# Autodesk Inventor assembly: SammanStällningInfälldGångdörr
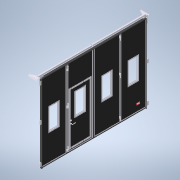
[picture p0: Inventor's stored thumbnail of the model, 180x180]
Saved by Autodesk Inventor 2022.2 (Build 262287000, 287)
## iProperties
Created: 2022-02
Part Number: SammanStällningInfälldGångdörr
Document SubType Name: Assembly
Designer: cl
Author: cl
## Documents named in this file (20)
- G:\AutoCad\Carl Lund\3D-modeller systemlösningar\3D-modell-systemlösning-2022\SammanStällningInfälldGångdörr.iam
- G:\AutoCad\Carl Lund\3D-modeller systemlösningar\3D-modell-systemlösning-2022\Parts\BladKomplett2022.iam
- G:\AutoCad\Carl Lund\3D-modeller systemlösningar\3D-modell-systemlösning-2022\Parts\MellanGångjärnH.ipt
- G:\AutoCad\Carl Lund\3D-modeller systemlösningar\3D-modell-systemlösning-2022\Parts\MellanGångjärnV.ipt
- G:\AutoCad\Carl Lund\3D-modeller systemlösningar\3D-modell-systemlösning-2022\Parts\Karmstyrning.ipt
- G:\AutoCad\Carl Lund\3D-modeller systemlösningar\3D-modell-systemlösning-2022\Parts\KarmgångjärnH.ipt
- G:\AutoCad\Carl Lund\3D-modeller systemlösningar\3D-modell-systemlösning-2022\Parts\KarmgångjärnV.ipt
- G:\AutoCad\Carl Lund\3D-modeller systemlösningar\3D-modell-systemlösning-2022\Parts\SidotätningUppe.ipt
- G:\AutoCad\Carl Lund\3D-modeller systemlösningar\3D-modell-systemlösning-2022\Parts\SidoTätning.ipt
- G:\AutoCad\Carl Lund\3D-modeller systemlösningar\3D-modell-systemlösning-2022\Parts\SläpList.ipt
- G:\AutoCad\Carl Lund\3D-modeller systemlösningar\3D-modell-systemlösning-2022\Parts\GummilistMellan.ipt
- G:\AutoCad\Carl Lund\3D-modeller systemlösningar\3D-modell-systemlösning-2022\Styrande.iam
- G:\AutoCad\Carl Lund\3D-modeller systemlösningar\3D-modell-systemlösning-2022\Parts\GarageregelHöger.ipt
- G:\AutoCad\Carl Lund\3D-modeller systemlösningar\3D-modell-systemlösning-2022\Parts\GarageregelVänster.ipt
- G:\AutoCad\Carl Lund\3D-modeller systemlösningar\3D-modell-systemlösning-2022\Parts\UppställningsbeslagHöger.ipt
- G:\AutoCad\Carl Lund\3D-modeller systemlösningar\3D-modell-systemlösning-2022\Parts\UppställningsbeslagVänster.ipt
- G:\AutoCad\Carl Lund\3D-modeller systemlösningar\3D-modell-systemlösning-2022\Parts\styrrulle.ipt
- G:\AutoCad\Carl Lund\3D-modeller systemlösningar\3D-modell-systemlösning-2022\Parts\Styrskena.ipt
- G:\AutoCad\Carl Lund\3D-modeller systemlösningar\3D-modell-systemlösning-2022\Parts\BladKomplettInfälld2022.iam
- G:\AutoCad\Carl Lund\3D-modeller systemlösningar\3D-modell-systemlösning-2022\Parts\Logga.ipt
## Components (50 placed, 18 different names)
1. BladKomplett2022:1 [sub-assembly] — Mate:1, Mate:2, Flush:1, Flush:2, Flush:3, Flush:8, Flush:28, Flush:29, Mate:28, Flush:30, Mate:42, Flush:73, Mate:39, Mate:43, Mate:47, Mate:48, Flush:99, Flush:100, Flush:101, Flush:102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
2. BladKomplett2022:2 [sub-assembly] — Flush:2, Flush:3, Flush:8, Flush:106, Mate:52, Flush:107, Flush:118, Flush:121, Mate:65, Flush:148, Flush:149, Mate:82, Flush:170, Flush:171, Flush:177
3. BladKomplett2022:3 [sub-assembly] — Flush:30, Flush:101, Flush:102, Mate:53, Flush:114, Flush:115
4. BladKomplett2022:4 [sub-assembly] — Flush:32, Flush:100, Flush:103, Mate:54, Flush:122, Flush:123, Flush:128, Mate:64, Flush:146, Flush:147
5. BladKomplett2022:5 [sub-assembly] — Flush:31, Flush:99, Flush:104, Flush:129, Mate:55, Flush:130, Mate:63, Flush:144, Flush:145, Mate:81, Flush:168, Flush:169
6. Logga:1 — Mate:181, Mate:182, Mate:183
7. BladKomplett2022:6 [sub-assembly] — Mate:28, Flush:28, Flush:29, Flush:31, Flush:32, Mate:38, Flush:74, Mate:49, Mate:50, Flush:131, Flush:134, Flush:137, Mate:56, Flush:138, Flush:139, Mate:58, Mate:59, Mate:62, Flush:142, Flush:143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
8. BladKomplettInfälld2022:1 [sub-assembly] — Flush:176, Flush:177, Flush:178, Mate:177, Flush:179, Flush:180, Flush:181, Mate:178, Flush:187, Flush:188, Flush:189, Mate:180, Flush:190
9. GarageregelHöger:1 — Flush:156, Flush:157, Flush:158
10. GarageregelHöger:2 — Mate:77, Flush:154, Flush:155, Flush:156, Flush:157, Flush:158
11. GarageregelVänster:1 — Flush:161, Flush:162, Flush:163
12. GarageregelVänster:2 — Mate:78, Flush:159, Flush:160, Flush:161, Flush:162, Flush:163
13. Karmstyrning:2 — Mate:38, Mate:56, Flush:138, Flush:141
14. Karmstyrning:3 — Mate:39, Mate:43, Flush:140
15. Karmstyrning:4 — Mate:42, Mate:60, Mate:61, Flush:141
16. KarmgångjärnH:1 — Flush:74, Mate:49, Mate:50, Flush:166, Flush:167, Mate:80
17. KarmgångjärnV:1 — Flush:73, Mate:47, Mate:48, Flush:164, Flush:165, Mate:79
18. Karmstyrning:1 — Flush:139, Mate:58, Mate:59, Flush:140
19. MellanGångjärnV:3 — Flush:110, Flush:111, Flush:113
20. MellanGångjärnV:2 — Flush:108, Flush:109, Flush:110, Flush:111, Flush:112
21. MellanGångjärnV:1 — Flush:106, Mate:52, Flush:107, Flush:108, Flush:109
22. MellanGångjärnH:2 — Flush:116, Flush:117, Flush:118, Flush:119, Flush:120
23. MellanGångjärnH:3 — Flush:119, Flush:120, Flush:121
24. MellanGångjärnH:1 — Mate:53, Flush:114, Flush:115, Flush:116, Flush:117
25. MellanGångjärnV:6 — Flush:124, Flush:125, Flush:126, Flush:127, Flush:128
26. MellanGångjärnV:5 — Flush:126, Flush:127, Flush:129
27. MellanGångjärnV:4 — Mate:54, Flush:122, Flush:123, Flush:124, Flush:125
28. MellanGångjärnH:5 — Flush:132, Flush:133, Flush:134
29. MellanGångjärnH:6 — Flush:135, Flush:136, Flush:137
30. MellanGångjärnH:4 — Mate:55, Flush:130, Flush:131, Flush:132, Flush:133, Flush:135, Flush:136
31. MellanGångjärnV:7 — Flush:181, Mate:178, Flush:182, Flush:183, Flush:184, Flush:185, Flush:186
32. MellanGångjärnV:8 — Flush:183, Flush:184, Flush:187
33. MellanGångjärnV:9 — Flush:185, Flush:186, Flush:188
34. GummilistMellan:6 — Mate:177, Flush:179, Flush:180
35. GummilistMellan:2 — Mate:63, Flush:144, Flush:145
36. GummilistMellan:3 — Mate:64, Flush:146, Flush:147
37. GummilistMellan:4 — Mate:65, Flush:148, Flush:149
38. GummilistMellan:5 — Mate:66, Flush:150, Flush:151
39. SidotätningUppe:1 — Mate:67, Mate:68, Flush:152, Mate:71, Mate:74
40. SidoTätning:1 — Mate:69, Mate:70, Mate:71, Mate:76
41. SidoTätning:2 — Mate:72, Mate:73, Mate:74
42. SläpList:1 — Mate:75, Flush:153, Mate:76
43. GummilistMellan:1 — Mate:62, Flush:142, Flush:143
44. styrrulle:3 — Flush:189, Mate:180, Flush:190
45. UppställningsbeslagVänster:1 — Flush:166, Flush:167, Mate:80
46. styrrulle:1 — Mate:81, Flush:168, Flush:169
47. styrrulle:2 — Mate:82, Flush:170, Flush:171
48. Styrskena:1 — Mate:83, Flush:172, Flush:174, Mate:176, Flush:175, Mate:179
49. Styrskena:2 — Flush:174, Mate:176, Flush:175
50. UppställningsbeslagHöger:1 — Flush:164, Flush:165, Mate:79, Mate:83, Flush:172, Mate:179
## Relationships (151: Flush 101, Mate 50)
- Mate:1: BladKomplett2022:1
- Mate:2: BladKomplett2022:1
- Flush:1: BladKomplett2022:1
- Flush:2: BladKomplett2022:1 ↔ BladKomplett2022:2
- Flush:3: BladKomplett2022:1 ↔ BladKomplett2022:2
- Flush:8: BladKomplett2022:1 ↔ BladKomplett2022:2
- Mate:28: BladKomplett2022:1 ↔ BladKomplett2022:6
- Flush:28: BladKomplett2022:1 ↔ BladKomplett2022:6
- Flush:29: BladKomplett2022:1 ↔ BladKomplett2022:6
- Flush:30: BladKomplett2022:1 ↔ BladKomplett2022:3
- Flush:31: BladKomplett2022:5 ↔ BladKomplett2022:6
- Flush:32: BladKomplett2022:4 ↔ BladKomplett2022:6
- Mate:38: BladKomplett2022:6 ↔ Karmstyrning:2
- Mate:39: BladKomplett2022:1 ↔ Karmstyrning:3
- Mate:42: BladKomplett2022:1 ↔ Karmstyrning:4
- Mate:43: BladKomplett2022:1 ↔ Karmstyrning:3
- Flush:73: BladKomplett2022:1 ↔ KarmgångjärnV:1
- Mate:47: BladKomplett2022:1 ↔ KarmgångjärnV:1
- Mate:48: BladKomplett2022:1 ↔ KarmgångjärnV:1
- Flush:74: BladKomplett2022:6 ↔ KarmgångjärnH:1
- Mate:49: BladKomplett2022:6 ↔ KarmgångjärnH:1
- Mate:50: BladKomplett2022:6 ↔ KarmgångjärnH:1
- Flush:99: BladKomplett2022:1 ↔ BladKomplett2022:5
- Flush:100: BladKomplett2022:1 ↔ BladKomplett2022:4
- Flush:101: BladKomplett2022:1 ↔ BladKomplett2022:3
- Flush:102: BladKomplett2022:1 ↔ BladKomplett2022:3
- Flush:103: BladKomplett2022:1 ↔ BladKomplett2022:4
- Flush:104: BladKomplett2022:1 ↔ BladKomplett2022:5
- Flush:106: BladKomplett2022:2 ↔ MellanGångjärnV:1
- Mate:52: BladKomplett2022:2 ↔ MellanGångjärnV:1
- Flush:107: BladKomplett2022:2 ↔ MellanGångjärnV:1
- Flush:108: MellanGångjärnV:2 ↔ MellanGångjärnV:1
- Flush:109: MellanGångjärnV:2 ↔ MellanGångjärnV:1
- Flush:110: MellanGångjärnV:3 ↔ MellanGångjärnV:2
- Flush:111: MellanGångjärnV:3 ↔ MellanGångjärnV:2
- Flush:112: BladKomplett2022:1 ↔ MellanGångjärnV:2
- Flush:113: BladKomplett2022:1 ↔ MellanGångjärnV:3
- Mate:53: BladKomplett2022:3 ↔ MellanGångjärnH:1
- Flush:114: BladKomplett2022:3 ↔ MellanGångjärnH:1
- Flush:115: BladKomplett2022:3 ↔ MellanGångjärnH:1
- Flush:116: MellanGångjärnH:2 ↔ MellanGångjärnH:1
- Flush:117: MellanGångjärnH:2 ↔ MellanGångjärnH:1
- Flush:118: BladKomplett2022:2 ↔ MellanGångjärnH:2
- Flush:119: MellanGångjärnH:2 ↔ MellanGångjärnH:3
- Flush:120: MellanGångjärnH:2 ↔ MellanGångjärnH:3
- Flush:121: BladKomplett2022:2 ↔ MellanGångjärnH:3
- Mate:54: BladKomplett2022:4 ↔ MellanGångjärnV:4
- Flush:122: BladKomplett2022:4 ↔ MellanGångjärnV:4
- Flush:123: BladKomplett2022:4 ↔ MellanGångjärnV:4
- Flush:124: MellanGångjärnV:6 ↔ MellanGångjärnV:4
- Flush:125: MellanGångjärnV:6 ↔ MellanGångjärnV:4
- Flush:126: MellanGångjärnV:6 ↔ MellanGångjärnV:5
- Flush:127: MellanGångjärnV:6 ↔ MellanGångjärnV:5
- Flush:128: BladKomplett2022:4 ↔ MellanGångjärnV:6
- Flush:129: BladKomplett2022:5 ↔ MellanGångjärnV:5
- Mate:55: BladKomplett2022:5 ↔ MellanGångjärnH:4
- Flush:130: BladKomplett2022:5 ↔ MellanGångjärnH:4
- Flush:131: BladKomplett2022:6 ↔ MellanGångjärnH:4
- Flush:132: MellanGångjärnH:5 ↔ MellanGångjärnH:4
- Flush:133: MellanGångjärnH:5 ↔ MellanGångjärnH:4
- Flush:134: BladKomplett2022:6 ↔ MellanGångjärnH:5
- Flush:135: MellanGångjärnH:6 ↔ MellanGångjärnH:4
- Flush:136: MellanGångjärnH:6 ↔ MellanGångjärnH:4
- Flush:137: BladKomplett2022:6 ↔ MellanGångjärnH:6
- Mate:56: BladKomplett2022:6 ↔ Karmstyrning:2
- Flush:138: BladKomplett2022:6 ↔ Karmstyrning:2
- Flush:139: BladKomplett2022:6 ↔ Karmstyrning:1
- Mate:58: BladKomplett2022:6 ↔ Karmstyrning:1
- Mate:59: BladKomplett2022:6 ↔ Karmstyrning:1
- Flush:140: Karmstyrning:3 ↔ Karmstyrning:1
- Mate:60: BladKomplett2022:1 ↔ Karmstyrning:4
- Mate:61: BladKomplett2022:1 ↔ Karmstyrning:4
- Flush:141: Karmstyrning:2 ↔ Karmstyrning:4
- Mate:62: BladKomplett2022:6 ↔ GummilistMellan:1
- Flush:142: BladKomplett2022:6 ↔ GummilistMellan:1
- Flush:143: BladKomplett2022:6 ↔ GummilistMellan:1
- Mate:63: BladKomplett2022:5 ↔ GummilistMellan:2
- Flush:144: BladKomplett2022:5 ↔ GummilistMellan:2
- Flush:145: BladKomplett2022:5 ↔ GummilistMellan:2
- Mate:64: BladKomplett2022:4 ↔ GummilistMellan:3
- Flush:146: BladKomplett2022:4 ↔ GummilistMellan:3
- Flush:147: BladKomplett2022:4 ↔ GummilistMellan:3
- Mate:65: BladKomplett2022:2 ↔ GummilistMellan:4
- Flush:148: BladKomplett2022:2 ↔ GummilistMellan:4
- Flush:149: BladKomplett2022:2 ↔ GummilistMellan:4
- Mate:66: BladKomplett2022:1 ↔ GummilistMellan:5
- Flush:150: BladKomplett2022:1 ↔ GummilistMellan:5
- Flush:151: BladKomplett2022:1 ↔ GummilistMellan:5
- Mate:67: BladKomplett2022:1 ↔ SidotätningUppe:1
- Mate:68: BladKomplett2022:1 ↔ SidotätningUppe:1
- Flush:152: BladKomplett2022:6 ↔ SidotätningUppe:1
- Mate:69: BladKomplett2022:6 ↔ SidoTätning:1
- Mate:70: BladKomplett2022:6 ↔ SidoTätning:1
- Mate:71: SidotätningUppe:1 ↔ SidoTätning:1
- Mate:72: BladKomplett2022:1 ↔ SidoTätning:2
- Mate:73: BladKomplett2022:1 ↔ SidoTätning:2
- Mate:74: SidotätningUppe:1 ↔ SidoTätning:2
- Mate:75: BladKomplett2022:1 ↔ SläpList:1
- Flush:153: BladKomplett2022:1 ↔ SläpList:1
- Mate:76: SidoTätning:1 ↔ SläpList:1
- Mate:77: BladKomplett2022:1 ↔ GarageregelHöger:2
- Flush:154: BladKomplett2022:1 ↔ GarageregelHöger:2
- Flush:155: BladKomplett2022:1 ↔ GarageregelHöger:2
- Flush:156: GarageregelHöger:1 ↔ GarageregelHöger:2
- Flush:157: GarageregelHöger:1 ↔ GarageregelHöger:2
- Flush:158: GarageregelHöger:1 ↔ GarageregelHöger:2
- Mate:78: BladKomplett2022:6 ↔ GarageregelVänster:2
- Flush:159: BladKomplett2022:6 ↔ GarageregelVänster:2
- Flush:160: BladKomplett2022:6 ↔ GarageregelVänster:2
- Flush:161: GarageregelVänster:1 ↔ GarageregelVänster:2
- Flush:162: GarageregelVänster:1 ↔ GarageregelVänster:2
- Flush:163: GarageregelVänster:1 ↔ GarageregelVänster:2
- Flush:164: KarmgångjärnV:1 ↔ UppställningsbeslagHöger:1
- Flush:165: KarmgångjärnV:1 ↔ UppställningsbeslagHöger:1
- Mate:79: KarmgångjärnV:1 ↔ UppställningsbeslagHöger:1
- Flush:166: KarmgångjärnH:1 ↔ UppställningsbeslagVänster:1
- Flush:167: KarmgångjärnH:1 ↔ UppställningsbeslagVänster:1
- Mate:80: KarmgångjärnH:1 ↔ UppställningsbeslagVänster:1
- Mate:81: BladKomplett2022:5 ↔ styrrulle:1
- Flush:168: BladKomplett2022:5 ↔ styrrulle:1
- Flush:169: BladKomplett2022:5 ↔ styrrulle:1
- Mate:82: BladKomplett2022:2 ↔ styrrulle:2
- Flush:170: BladKomplett2022:2 ↔ styrrulle:2
- Flush:171: BladKomplett2022:2 ↔ styrrulle:2
- Mate:83: Styrskena:1 ↔ UppställningsbeslagHöger:1
- Flush:172: Styrskena:1 ↔ UppställningsbeslagHöger:1
- Flush:174: Styrskena:1 ↔ Styrskena:2
- Mate:176: Styrskena:1 ↔ Styrskena:2
- Flush:175: Styrskena:1 ↔ Styrskena:2
- Flush:176: BladKomplett2022:1 ↔ BladKomplettInfälld2022:1
- Flush:177: BladKomplett2022:2 ↔ BladKomplettInfälld2022:1
- Flush:178: BladKomplett2022:1 ↔ BladKomplettInfälld2022:1
- Mate:177: BladKomplettInfälld2022:1 ↔ GummilistMellan:6
- Flush:179: BladKomplettInfälld2022:1 ↔ GummilistMellan:6
- Flush:180: BladKomplettInfälld2022:1 ↔ GummilistMellan:6
- Flush:181: BladKomplettInfälld2022:1 ↔ MellanGångjärnV:7
- Mate:178: BladKomplettInfälld2022:1 ↔ MellanGångjärnV:7
- Flush:182: BladKomplett2022:1 ↔ MellanGångjärnV:7
- Flush:183: MellanGångjärnV:7 ↔ MellanGångjärnV:8
- Flush:184: MellanGångjärnV:7 ↔ MellanGångjärnV:8
- Flush:185: MellanGångjärnV:7 ↔ MellanGångjärnV:9
- Flush:186: MellanGångjärnV:7 ↔ MellanGångjärnV:9
- Flush:187: BladKomplettInfälld2022:1 ↔ MellanGångjärnV:8
- Flush:188: BladKomplettInfälld2022:1 ↔ MellanGångjärnV:9
- Mate:179: Styrskena:1 ↔ UppställningsbeslagHöger:1
- Flush:189: BladKomplettInfälld2022:1 ↔ styrrulle:3
- Mate:180: BladKomplettInfälld2022:1 ↔ styrrulle:3
- Flush:190: BladKomplettInfälld2022:1 ↔ styrrulle:3
- Mate:181: Logga:1 ↔ BladKomplett2022:6
- Mate:182: Logga:1 ↔ BladKomplett2022:6
- Mate:183: Logga:1 ↔ BladKomplett2022:6
## Named parameters: Blad2 = 0, Blad3 = 0, Blad4 = 0, Blad5 = 1012.5 mm, MGJ12Djup = 48 mm, MGJ56Djup = 0, MGJ56Bredd = 0, MGJ23Djup = 48 mm, MGJ45Djup = 48 mm, GarageRegel5 = 0, GarageRegel6 = 0, BladBredd = 987.5 mm, Fönsterhöjd = 862 mm, Blad2_1 = 0, Blad3_1 = 0, Blad4_1 = 0, Blad5_1 = 1012.5 mm, Blad6 = 2025 mm, MGJ12Djup_1 = 48 mm, MGJ2Djup = 0, MGJ2Bredd = 5012.5 mm, MGJ56Djup_1 = 0, MGJ56Bredd_1 = 0, MGJ23Djup_1 = 48 mm, MGJ45Djup_1 = 48 mm, GarageRegel5_1 = 0, GarageRegel6_1 = 0, Styrrulle2Djup = 0, FönsterhöjdStyrning = 862 mm, FönsterKarm = 54 mm, AndraGlasraden = 0, BrösthöjdStyrning2 = 0.0001 mm, Infälldstyr = 1012.5 mm
